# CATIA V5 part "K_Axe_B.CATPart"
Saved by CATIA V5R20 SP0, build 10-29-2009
Part number: Axe_B
Bounding box of the stored display mesh (mm): x -12.5 to 12.5, y -12.5 to 12.5, z 0 to 86
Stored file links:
  G:\Khaled_CFAO_2011\ST2M\ST2M_GR2\echouteau\Khaled\CAD_ThinkMotion\K_Axe_B.CATPart
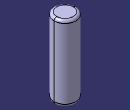
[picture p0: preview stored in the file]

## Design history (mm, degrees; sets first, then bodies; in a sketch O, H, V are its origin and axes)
AxisSystem1: origin (0, 0, 0), X (1, 0, 0), Y (0, 1, 0), Z (0, 0, 1)
Body1 (main body)
  Sketch1 on XY plane of AxisSystem1, origin (0, 0, 0), H (1, 0, 0), V (0, 1, 0)
    circle A1 centre (0, 0) radius 12.5
    radius A1 = 12.5
  Pad1: profile Sketch1, direction (0, 0, 1), length 86
  Fillet1: radius 3, on end face of Pad1
  Fillet2: radius 3, on edge [start face of Pad1 | face of Pad1 from Sketch1.A1]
